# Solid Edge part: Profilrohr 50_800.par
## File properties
Username: ahadarics
Dokumentum tartalom típus: 0
Author: ahadarics
Last saved by: ahadarics
Revision: 91
Sűrűség: 0,000 kg/m^3
Pontosság: 0,990
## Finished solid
Body 1: solid body, 175 faces, 519 edges, 346 vertices.
  Faces by surface: cylinder 107, plane 68
  Edges by curve: line 305, circle 214
Bounding box of the edges (mm): 60.200 x 60.200 x 844.000, from (-30.1, -30.1, -784.5) to (30.1, 30.1, 59.5).
Cylindrical faces by radius (mm): R0.1 x16, R0.2 x30, R0.5 x28, R1 x8, R3.75 x8, R5 x4, R6 x4, R25 x1, R27 x8
Planar faces by outward normal: +x 6, +y 6, +z 1, -x 4, -y 4, -z 1, oblique 46
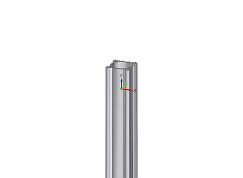
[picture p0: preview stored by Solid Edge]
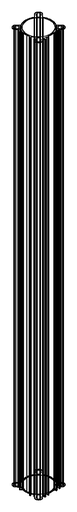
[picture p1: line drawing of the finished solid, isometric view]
